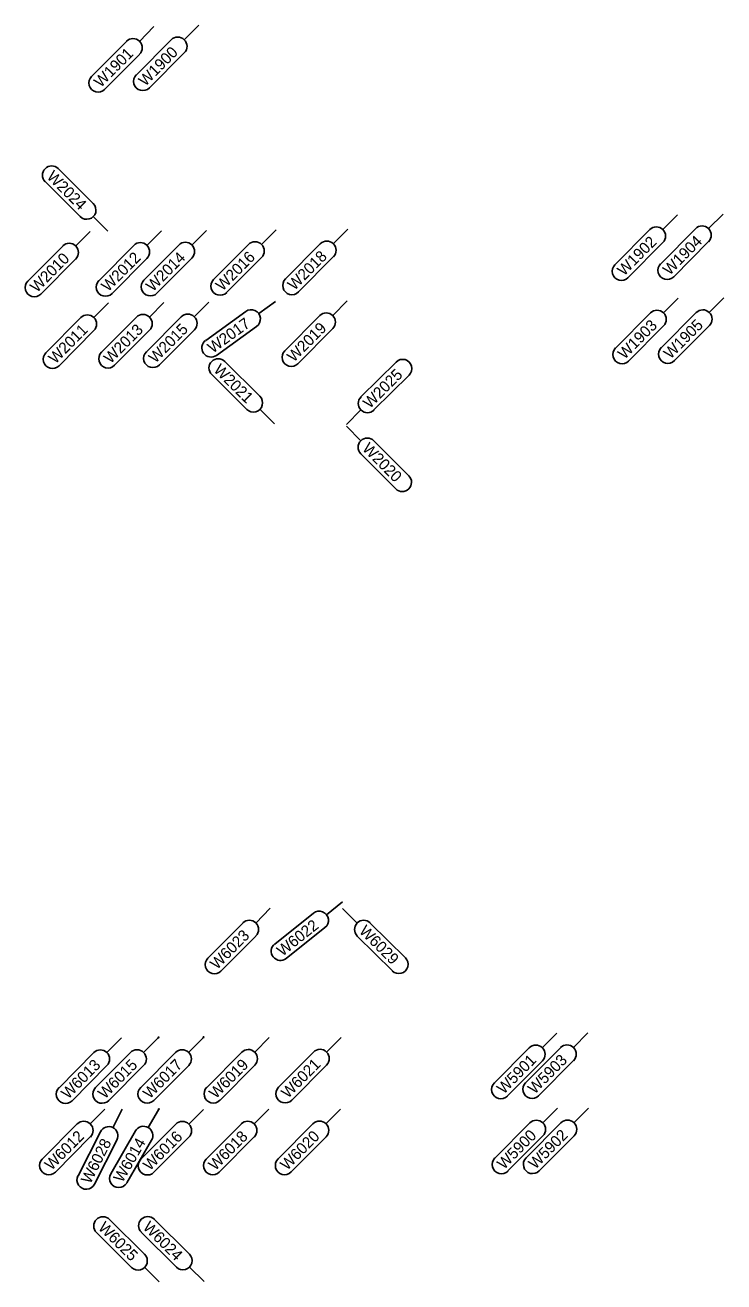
# Model space of a CAD drawing. Extents: x 12479652 to 12487250, y 9842710 to 9846560.
# Drawn here: x 12483258.6 to 12483336.5, y 9842730.8 to 9842870.9 of the extents above; entities that cross this region are included whole.
import ezdxf

# ---------------------------------------------------------------- set-up
doc = ezdxf.new("R2010")
doc.units = 0
doc.layers.add('_CIVIL_CONSTRUCTION', color=7, linetype='Continuous')
doc.layers.add('TextAlignmentLrg', color=7, linetype='Continuous')

msp = doc.modelspace()

# ---------------------------------------------------------------- linework, layer by layer
at = {"layer": '_CIVIL_CONSTRUCTION'}
for p, q in [((12483272.98, 9842870.75), (12483271.36, 9842869.11)), ((12483277.98, 9842870.92), (12483276.36, 9842869.29)), ((12483266.02, 9842865.2), (12483269.91, 9842869.11)), ((12483271.02, 9842865.37), (12483274.91, 9842869.28)), ((12483271.36, 9842867.66), (12483267.47, 9842863.75)), ((12483276.36, 9842867.84), (12483272.47, 9842863.92)), ((12483262.31, 9842854.92), (12483266.22, 9842851.03)), ((12483264.77, 9842849.58), (12483260.86, 9842853.47)), ((12483267.85, 9842847.96), (12483266.22, 9842849.58)), ((12483331.29, 9842849.76), (12483329.67, 9842848.12)), ((12483336.39, 9842849.86), (12483334.77, 9842848.23)), ((12483265.89, 9842847.93), (12483264.27, 9842846.3)), ((12483273.82, 9842847.99), (12483272.2, 9842846.36)), ((12483278.82, 9842848.04), (12483277.2, 9842846.4)), ((12483286.58, 9842848.1), (12483284.96, 9842846.47)), ((12483294.58, 9842848.17), (12483292.96, 9842846.54)), ((12483324.33, 9842844.21), (12483328.22, 9842848.12)), ((12483329.43, 9842844.31), (12483333.32, 9842848.22)), ((12483279.62, 9842842.55), (12483283.51, 9842846.46)), ((12483287.62, 9842842.62), (12483291.51, 9842846.53)), ((12483329.67, 9842846.67), (12483325.78, 9842842.76)), ((12483334.77, 9842846.78), (12483330.88, 9842842.86)), ((12483258.93, 9842842.38), (12483262.82, 9842846.29)), ((12483266.86, 9842842.45), (12483270.75, 9842846.36)), ((12483271.86, 9842842.49), (12483275.75, 9842846.4)), ((12483292.96, 9842845.08), (12483289.07, 9842841.17)), ((12483264.27, 9842844.85), (12483260.38, 9842840.93)), ((12483272.2, 9842844.91), (12483268.31, 9842841)), ((12483277.2, 9842844.95), (12483273.31, 9842841.04)), ((12483284.96, 9842845.02), (12483281.07, 9842841.11)), ((12483267.91, 9842839.95), (12483266.28, 9842838.31)), ((12483274.09, 9842840), (12483272.47, 9842838.37)), ((12483279.1, 9842840.04), (12483277.47, 9842838.41)), ((12483286.51, 9842840.1), (12483284.65, 9842838.76)), ((12483294.52, 9842840.17), (12483292.9, 9842838.53)), ((12483331.37, 9842840.47), (12483329.74, 9842838.84)), ((12483336.47, 9842840.51), (12483334.84, 9842838.88)), ((12483260.94, 9842834.4), (12483264.83, 9842838.31)), ((12483267.13, 9842834.45), (12483271.02, 9842838.36)), ((12483272.13, 9842834.49), (12483276.02, 9842838.4)), ((12483278.74, 9842835.77), (12483283.22, 9842838.99)), ((12483287.55, 9842834.62), (12483291.44, 9842838.53)), ((12483324.4, 9842834.92), (12483328.29, 9842838.83)), ((12483329.5, 9842834.96), (12483333.39, 9842838.88)), ((12483266.29, 9842836.86), (12483262.4, 9842832.95)), ((12483272.48, 9842836.91), (12483268.59, 9842833)), ((12483277.48, 9842836.96), (12483273.59, 9842833.04)), ((12483284.41, 9842837.33), (12483279.94, 9842834.1)), ((12483292.9, 9842837.08), (12483289.01, 9842833.17)), ((12483329.75, 9842837.39), (12483325.86, 9842833.47)), ((12483334.85, 9842837.43), (12483330.96, 9842833.52)), ((12483280.86, 9842833.43), (12483284.77, 9842829.54)), ((12483299.96, 9842833.36), (12483296.04, 9842829.47)), ((12483283.33, 9842828.08), (12483279.41, 9842831.97)), ((12483297.49, 9842828.02), (12483301.4, 9842831.91)), ((12483286.41, 9842826.46), (12483284.78, 9842828.09)), ((12483294.41, 9842826.4), (12483296.04, 9842828.02)), ((12483294.41, 9842826.22), (12483296.03, 9842824.59)), ((12483301.37, 9842820.67), (12483297.48, 9842824.58)), ((12483296.02, 9842823.14), (12483299.91, 9842819.22)), ((12483285.94, 9842772.46), (12483284.32, 9842770.82)), ((12483294, 9842773.18), (12483292.2, 9842771.75)), ((12483293.99, 9842772.44), (12483295.62, 9842770.82)), ((12483278.98, 9842766.91), (12483282.87, 9842770.82)), ((12483286.44, 9842768.48), (12483290.75, 9842771.92)), ((12483297.07, 9842770.82), (12483300.99, 9842766.93)), ((12483292.03, 9842770.31), (12483287.71, 9842766.88)), ((12483284.32, 9842769.37), (12483280.44, 9842765.46)), ((12483299.54, 9842765.48), (12483295.63, 9842769.37)), ((12483317.86, 9842758.53), (12483316.24, 9842756.9)), ((12483321.33, 9842758.56), (12483319.71, 9842756.93)), ((12483269.36, 9842758.01), (12483267.74, 9842756.38)), ((12483273.45, 9842758.02), (12483271.82, 9842756.39)), ((12483278.46, 9842758.03), (12483276.84, 9842756.4)), ((12483285.83, 9842758.05), (12483284.21, 9842756.42)), ((12483293.83, 9842758.07), (12483292.21, 9842756.44)), ((12483310.9, 9842752.99), (12483314.79, 9842756.9)), ((12483314.37, 9842753.01), (12483318.26, 9842756.92)), ((12483262.4, 9842752.46), (12483266.29, 9842756.37)), ((12483266.48, 9842752.47), (12483270.37, 9842756.38)), ((12483271.5, 9842752.48), (12483275.39, 9842756.39)), ((12483278.86, 9842752.5), (12483282.75, 9842756.41)), ((12483286.87, 9842752.52), (12483290.75, 9842756.43)), ((12483316.25, 9842755.45), (12483312.36, 9842751.54)), ((12483319.72, 9842755.48), (12483315.83, 9842751.57)), ((12483267.74, 9842754.93), (12483263.85, 9842751.01)), ((12483271.83, 9842754.94), (12483267.94, 9842751.02)), ((12483276.85, 9842754.95), (12483272.96, 9842751.03)), ((12483284.21, 9842754.97), (12483280.32, 9842751.05)), ((12483292.21, 9842754.98), (12483288.32, 9842751.07)), ((12483267.51, 9842750.05), (12483265.88, 9842748.42)), ((12483269.43, 9842750.06), (12483268.39, 9842748)), ((12483273.48, 9842750.01), (12483272.33, 9842748.01)), ((12483278.48, 9842750.03), (12483276.86, 9842748.4)), ((12483285.76, 9842750.05), (12483284.14, 9842748.42)), ((12483293.76, 9842750.07), (12483292.14, 9842748.43)), ((12483317.93, 9842750.17), (12483316.3, 9842748.54)), ((12483321.4, 9842750.18), (12483319.77, 9842748.55)), ((12483260.54, 9842744.5), (12483264.43, 9842748.42)), ((12483271.52, 9842744.48), (12483275.41, 9842748.39)), ((12483278.8, 9842744.5), (12483282.69, 9842748.41)), ((12483286.8, 9842744.52), (12483290.69, 9842748.43)), ((12483310.96, 9842744.62), (12483314.85, 9842748.54)), ((12483314.43, 9842744.63), (12483318.32, 9842748.55)), ((12483264.52, 9842742.63), (12483267.01, 9842747.55)), ((12483268.17, 9842742.86), (12483270.93, 9842747.64)), ((12483292.15, 9842746.98), (12483288.26, 9842743.07)), ((12483316.31, 9842747.09), (12483312.42, 9842743.18)), ((12483319.78, 9842747.1), (12483315.89, 9842743.19)), ((12483265.89, 9842746.97), (12483262, 9842743.06)), ((12483268.84, 9842746.63), (12483266.35, 9842741.7)), ((12483272.71, 9842746.61), (12483269.94, 9842741.84)), ((12483276.86, 9842746.95), (12483272.97, 9842743.03)), ((12483284.15, 9842746.97), (12483280.26, 9842743.05)), ((12483268.02, 9842737.78), (12483271.93, 9842733.89)), ((12483273.02, 9842737.8), (12483276.93, 9842733.91)), ((12483270.49, 9842732.43), (12483266.57, 9842736.32)), ((12483275.49, 9842732.46), (12483271.57, 9842736.34)), ((12483273.57, 9842730.82), (12483271.94, 9842732.44)), ((12483278.57, 9842730.84), (12483276.94, 9842732.46))]:
    msp.add_line(p, q, dxfattribs=at)
for centre, start, end in [((12483270.64, 9842868.39), 315.1702, 135.1702), ((12483275.63, 9842868.56), 315.1702, 135.1702), ((12483266.75, 9842864.47), 135.1702, 315.1702), ((12483271.74, 9842864.65), 135.1702, 315.1702), ((12483261.58, 9842854.19), 45.1702, 225.1702), ((12483265.49, 9842850.3), 225.1702, 45.1702), ((12483328.94, 9842847.4), 315.1702, 135.1702), ((12483334.04, 9842847.5), 315.1702, 135.1702), ((12483263.54, 9842845.57), 315.1702, 135.1702), ((12483271.47, 9842845.64), 315.1702, 135.1702), ((12483276.47, 9842845.68), 315.1702, 135.1702), ((12483284.24, 9842845.74), 315.1702, 135.1702), ((12483292.24, 9842845.81), 315.1702, 135.1702), ((12483325.05, 9842843.48), 135.1702, 315.1702), ((12483330.15, 9842843.59), 135.1702, 315.1702), ((12483259.65, 9842841.66), 135.1702, 315.1702), ((12483267.58, 9842841.72), 135.1702, 315.1702), ((12483272.58, 9842841.76), 135.1702, 315.1702), ((12483280.35, 9842841.83), 135.1702, 315.1702), ((12483288.35, 9842841.9), 135.1702, 315.1702), ((12483265.56, 9842837.59), 315.1702, 135.1702), ((12483271.75, 9842837.64), 315.1702, 135.1702), ((12483276.75, 9842837.68), 315.1702, 135.1702), ((12483283.81, 9842838.16), 305.7545, 125.7545), ((12483292.17, 9842837.81), 315.1702, 135.1702), ((12483329.02, 9842838.11), 315.1702, 135.1702), ((12483334.12, 9842838.15), 315.1702, 135.1702), ((12483279.34, 9842834.94), 125.7545, 305.7545), ((12483261.67, 9842833.67), 135.1702, 315.1702), ((12483267.86, 9842833.72), 135.1702, 315.1702), ((12483272.86, 9842833.77), 135.1702, 315.1702), ((12483288.28, 9842833.89), 135.1702, 315.1702), ((12483325.13, 9842834.2), 135.1702, 315.1702), ((12483330.23, 9842834.24), 135.1702, 315.1702), ((12483280.14, 9842832.7), 45.1702, 225.1702), ((12483300.68, 9842832.63), 314.8298, 134.8298), ((12483284.05, 9842828.81), 225.1702, 45.1702), ((12483296.77, 9842828.74), 134.8298, 314.8298), ((12483296.75, 9842823.86), 44.8298, 224.8298), ((12483300.64, 9842819.95), 224.8298, 44.8298), ((12483283.6, 9842770.1), 315.1702, 135.1702), ((12483291.39, 9842771.11), 308.4933, 128.4933), ((12483296.35, 9842770.1), 45.1702, 225.1702), ((12483287.07, 9842767.68), 128.4933, 308.4933), ((12483279.71, 9842766.18), 135.1702, 315.1702), ((12483300.26, 9842766.21), 225.1702, 45.1702), ((12483315.52, 9842756.18), 315.1702, 135.1702), ((12483318.99, 9842756.2), 315.1702, 135.1702), ((12483267.01, 9842755.65), 315.1702, 135.1702), ((12483271.1, 9842755.66), 315.1702, 135.1702), ((12483276.12, 9842755.67), 315.1702, 135.1702), ((12483283.48, 9842755.69), 315.1702, 135.1702), ((12483291.48, 9842755.71), 315.1702, 135.1702), ((12483311.63, 9842752.26), 135.1702, 315.1702), ((12483315.1, 9842752.29), 135.1702, 315.1702), ((12483263.13, 9842751.74), 135.1702, 315.1702), ((12483267.21, 9842751.75), 135.1702, 315.1702), ((12483272.23, 9842751.76), 135.1702, 315.1702), ((12483279.59, 9842751.78), 135.1702, 315.1702), ((12483287.59, 9842751.79), 135.1702, 315.1702), ((12483265.16, 9842747.69), 315.1702, 135.1702), ((12483276.14, 9842747.67), 315.1702, 135.1702), ((12483283.42, 9842747.69), 315.1702, 135.1702), ((12483291.42, 9842747.71), 315.1702, 135.1702), ((12483315.58, 9842747.81), 315.1702, 135.1702), ((12483319.05, 9842747.82), 315.1702, 135.1702), ((12483267.93, 9842747.09), 333.1572, 153.1572), ((12483271.82, 9842747.13), 329.9519, 149.9519), ((12483261.27, 9842743.78), 135.1702, 315.1702), ((12483272.25, 9842743.76), 135.1702, 315.1702), ((12483279.53, 9842743.78), 135.1702, 315.1702), ((12483287.53, 9842743.79), 135.1702, 315.1702), ((12483311.69, 9842743.9), 135.1702, 315.1702), ((12483315.16, 9842743.91), 135.1702, 315.1702), ((12483269.05, 9842742.35), 149.9519, 329.9519), ((12483265.43, 9842742.17), 153.1572, 333.1572), ((12483267.3, 9842737.05), 45.1702, 225.1702), ((12483272.3, 9842737.07), 45.1702, 225.1702), ((12483271.21, 9842733.16), 225.1702, 45.1702), ((12483276.21, 9842733.18), 225.1702, 45.1702)]:
    msp.add_arc(centre, 1.03, start, end, dxfattribs=at)
at = {"layer": 'TextAlignmentLrg'}
for centre in [(12483273.49, 9842758.07), (12483278.51, 9842758.08), (12483273.53, 9842750.07)]:
    msp.add_circle(centre, 0.05, dxfattribs=at)

# ---------------------------------------------------------------- texts
at = {"layer": '_CIVIL_CONSTRUCTION'}
for s, rotation, p in [('W1901', 45.1702, (12483267.05, 9842863.88)), ('W1900', 45.1702, (12483272.01, 9842864.02)), ('W2024', 315.1702, (12483260.95, 9842853.93)), ('W1902', 45.1702, (12483325.34, 9842842.88)), ('W1904', 45.1702, (12483330.42, 9842842.95)), ('W2010', 45.1702, (12483259.93, 9842841.03)), ('W2012', 45.1702, (12483267.87, 9842841.12)), ('W2014', 45.1702, (12483272.85, 9842841.13)), ('W2016', 45.1702, (12483280.61, 9842841.2)), ('W2018', 45.1702, (12483288.62, 9842841.27)), ('W2017', 35.7545, (12483279.52, 9842834.28)), ('W1905', 45.1702, (12483330.52, 9842833.62)), ('W2011', 45.1702, (12483261.98, 9842833.08)), ('W2013', 45.1702, (12483268.14, 9842833.1)), ('W2015', 45.1702, (12483273.14, 9842833.15)), ('W2019', 45.1702, (12483288.56, 9842833.27)), ('W1903', 45.1702, (12483325.41, 9842833.58)), ('W2021', 315.1702, (12483279.54, 9842832.39)), ('W2025', 44.8298, (12483297.02, 9842828.1)), ('W2020', 314.8298, (12483296.1, 9842823.62)), ('W6022', 38.4933, (12483287.29, 9842767.04)), ('W6023', 45.1702, (12483279.99, 9842765.56)), ('W6029', 315.1702, (12483295.75, 9842769.82)), ('W6013', 45.1702, (12483263.4, 9842751.12)), ('W6015', 45.1702, (12483267.5, 9842751.13)), ('W6017', 45.1702, (12483272.51, 9842751.14)), ('W6019', 45.1702, (12483279.87, 9842751.15)), ('W6021', 45.1702, (12483287.9, 9842751.2)), ('W5901', 45.1702, (12483311.94, 9842751.67)), ('W5903', 45.1702, (12483315.38, 9842751.67)), ('W6012', 45.1702, (12483261.56, 9842743.17)), ('W6016', 45.1702, (12483272.52, 9842743.13)), ('W6018', 45.1702, (12483279.8, 9842743.15)), ('W6020', 45.1702, (12483287.8, 9842743.17)), ('W5900', 45.1702, (12483311.96, 9842743.27)), ('W5902', 45.1702, (12483315.45, 9842743.3)), ('W6028', 63.1572, (12483265.89, 9842741.65)), ('W6014', 59.9519, (12483269.47, 9842741.8)), ('W6025', 315.1702, (12483266.68, 9842736.77)), ('W6024', 315.1702, (12483271.66, 9842736.81))]:
    msp.add_text(s, height=1.25, rotation=rotation, dxfattribs=at).set_placement(p)

doc.saveas('drawing.dxf')
